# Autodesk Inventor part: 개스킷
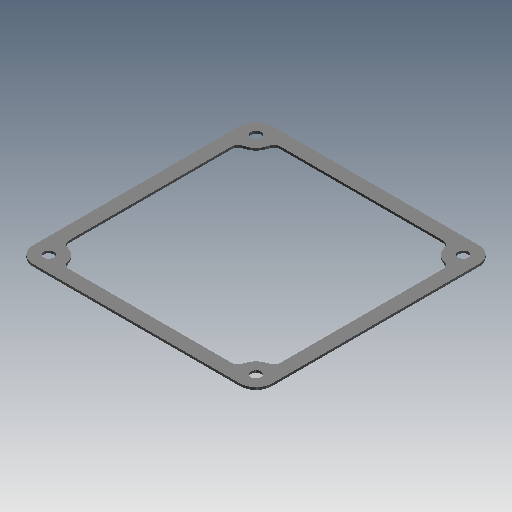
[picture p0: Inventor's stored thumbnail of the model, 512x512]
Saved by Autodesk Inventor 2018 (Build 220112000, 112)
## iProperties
Created: 2019-04
Part Number: 개스킷
Material: 고무
Document SubType Name: Modeling
Designer: mduedu
Density: 0.93 g/cm^3
Mass: 2.32152 g
Surface Area: 58.0824 cm^2
Volume: 2.49626 cm^3
Appearance: 고무 - 검은색 - 버전 1.1
Author: mduedu
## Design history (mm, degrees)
sketch "스케치1"
  geometry: L1 (52.5, 52.5)-(-52.5, 52.5); L2 (-52.5, 52.5)-(-52.5, -52.5); L3 (-52.5, -52.5)-(52.5, -52.5); L4 (52.5, -52.5)-(52.5, 52.5); L5 (52.5, 52.5)-(-52.5, -52.5); L6 (-52.5, 52.5)-(52.5, -52.5); 1 further point
  constraints: 12 end point, 2 midpoint, 2 parallel, 1 horizontal, 1 perpendicular
  dimensions: "d0" = 105 distance of L3.end L2.end; "d1" = 105 distance of L2.end L1.end
extrude "돌출1" new body sketch "스케치1" distance "d2" = 1; taper "d3" = 0 deg
sketch "스케치2"
  geometry: L1 (-52.5, -52.5)-(52.5, -52.5) reference; L2 (52.5, -52.5)-(52.5, 52.5) reference; L3 (52.5, 52.5)-(-52.5, 52.5) reference; L4 (-52.5, 52.5)-(-52.5, -52.5) reference; L5 (-46.5, 46.5)-(46.5, 46.5); L6 (46.5, 46.5)-(46.5, -46.5); L7 (46.5, -46.5)-(-46.5, -46.5); L8 (-46.5, -46.5)-(-46.5, 46.5); 1 further point
  constraints: 8 end point, 3 other
  dimensions: "d4" = 6 distance between parallel lines of L5 L3
extrude "돌출2" cut sketch "스케치2" extent not by distance; stored distance "d5" = 1; taper "d6" = 0 deg
fillet "모깎기1" dims "d7" = 7
sketch "스케치3"
  geometry: A1 r 7 centre (-45.5, 45.5) between (-45.5, 52.5) and (-52.5, 45.5) reference; A2 r 7 centre (-45.5, -45.5) between (-52.5, -45.5) and (-45.5, -52.5) reference; A3 r 7 centre (45.5, -45.5) between (45.5, -52.5) and (52.5, -45.5) reference; A4 r 7 centre (45.5, 45.5) between (52.5, 45.5) and (45.5, 52.5) reference; 5 further points
  constraints: 4 coincident, 4 vertical alignment, 8 other
extrude "돌출3" join sketch "스케치3" stored distance "d8" = 1; taper "d9" = 0 deg
fillet "모깎기2" dims "d10" = 3
sketch "스케치4"
  geometry: A1 r 7 centre (-45.5, 45.5) between (-45.5, 52.5) and (-52.5, 45.5) reference; A2 r 7 centre (45.5, 45.5) between (52.5, 45.5) and (45.5, 52.5) reference; A3 r 7 centre (45.5, -45.5) between (45.5, -52.5) and (52.5, -45.5) reference; A4 r 7 centre (-45.5, -45.5) between (-52.5, -45.5) and (-45.5, -52.5) reference; 5 further points
  constraints: 4 coincident
hole "구멍1" sketch "스케치4" at (-45.5, 45.5), (45.5, 45.5), (45.5, -45.5), (-45.5, -45.5) diameter "d11" = 4.5; stored, may be unused: countersink angle "d15" = 90 deg, drill point angle "d17" = 118 deg; dims "d12" = 6, "d13" = 4, "d14" = 2, "d16" = 8
node "솔리드1"
node "투영된 루프1"
